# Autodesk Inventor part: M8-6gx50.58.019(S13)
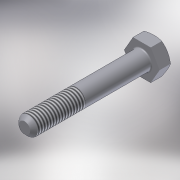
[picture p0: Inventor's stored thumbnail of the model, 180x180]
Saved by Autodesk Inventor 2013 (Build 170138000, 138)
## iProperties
Shininess: 20.0
Length Units: 11269
Angle Units: 11279
Time Units: 11290
Mass Units: 11283
Length Display Precision: 3
Angle Display Precision: 2
Created: 2001-07
Part Number: M8-6gx50.58.019(S13)
Material: Steel, Mild
Document SubType Name: Modeling
Designer: TEvgeniy
Density: 7.86 g/cm^3
Density: 0.0
Volumn: 0.0
Area: 0.0
PropertySet Name: Model Information
Control State: 0
Master: False
Checked Out: False
Checked Out Date: 2008-10-15
Last Check In Date: 2008-10-15
Author: TEvgeniy
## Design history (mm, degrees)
sketch "Sketch1"
  geometry: L1 (482.08, 469.325)-(474.575, 469.325); L2 (485.833, 462.825)-(482.08, 469.325); L3 (482.08, 456.325)-(485.833, 462.825); L4 (474.575, 456.325)-(482.08, 456.325); L5 (470.822, 462.825)-(474.575, 456.325); L6 (474.575, 469.325)-(470.822, 462.825); C1 r 6.5 at (478.327, 462.825)
  constraints: 12 end point, 6 tangent, 3 parallel, 1 centre point, 1 horizontal, 1 other
  dimensions: "d1" = 120 deg angle of L1 L2; "d3" = 120 deg angle of L5 L6; "d5" = 13 diameter of C1
extrude "ExtrusionBlind1" new body sketch "Sketch1" distance "d6" = 5.3; taper "d7" = 0 deg
sketch "Sketch2"
  geometry: C1 r 6.4 at (478.327, -462.825)
  constraints: 1 centre point
  dimensions: "d12" = 12.8 diameter of C1
extrude "ExtrusionThru1" sketch "Sketch2" stored distance "d13" = 0.13; taper "d14" = 60 deg
sketch "Sketch3"
  geometry: L1 (470.822, 462.825)-(471.322, 463.691); L2 (474.575, 469.325)-(475.575, 469.325); L3 (482.08, 469.325)-(482.58, 468.459); C1 r 4 at (478.327, 462.825); C2 r 6.5 at (478.327, 462.825)
  constraints: 6 end point, 3 tangent, 2 centre point, 1 coincident
  dimensions: "d16" = 8 diameter of C1
extrude "ExtrusionBlind2" join sketch "Sketch3" distance "d17" = 50; taper "d18" = 0 deg
fillet "Fillet1" dims "d19" = 0.5
feature "Резьба1" dims "d23" = 22, "d24" = 0
chamfer "Фаска2" distance "d25" = 1.6; stored, may be unused: second distance "d26" = 2, angle "d27" = 45 deg
body "Solid1"
other parameters: "d0" = 120 deg (derived), "d2" = 120 deg (derived), "d4" = 13 (derived), "d8" = 0, "d9" = 0, "d10" = 0, "d11" = 12.8 (derived), "d15" = 8 (derived)
